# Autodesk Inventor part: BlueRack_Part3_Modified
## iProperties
Shininess: 64.0
Length Units: 11272
Angle Units: 11279
Time Units: 11290
Mass Units: 11286
Length Display Precision: 3
Angle Display Precision: 2
Compacted: True
Part Number: BlueRack_Part3_Modified
Document SubType Name: Modeling
Created: 2004-12
Designer: John Blackburn
Material: Steel, Mild
Manufacturer: Standard
Standards Organization: Custom
Density: 0.0
Volumn: 0.0
Area: 0.0
PropertySet Name: Model Information
Control State: 0
Master: False
Checked Out: False
Author: John Blackburn
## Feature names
1. Extrusion1
2. Hole1
3. Hole3
4. Rectangular Pattern3
5. Hole4
6. Rectangular Pattern4
